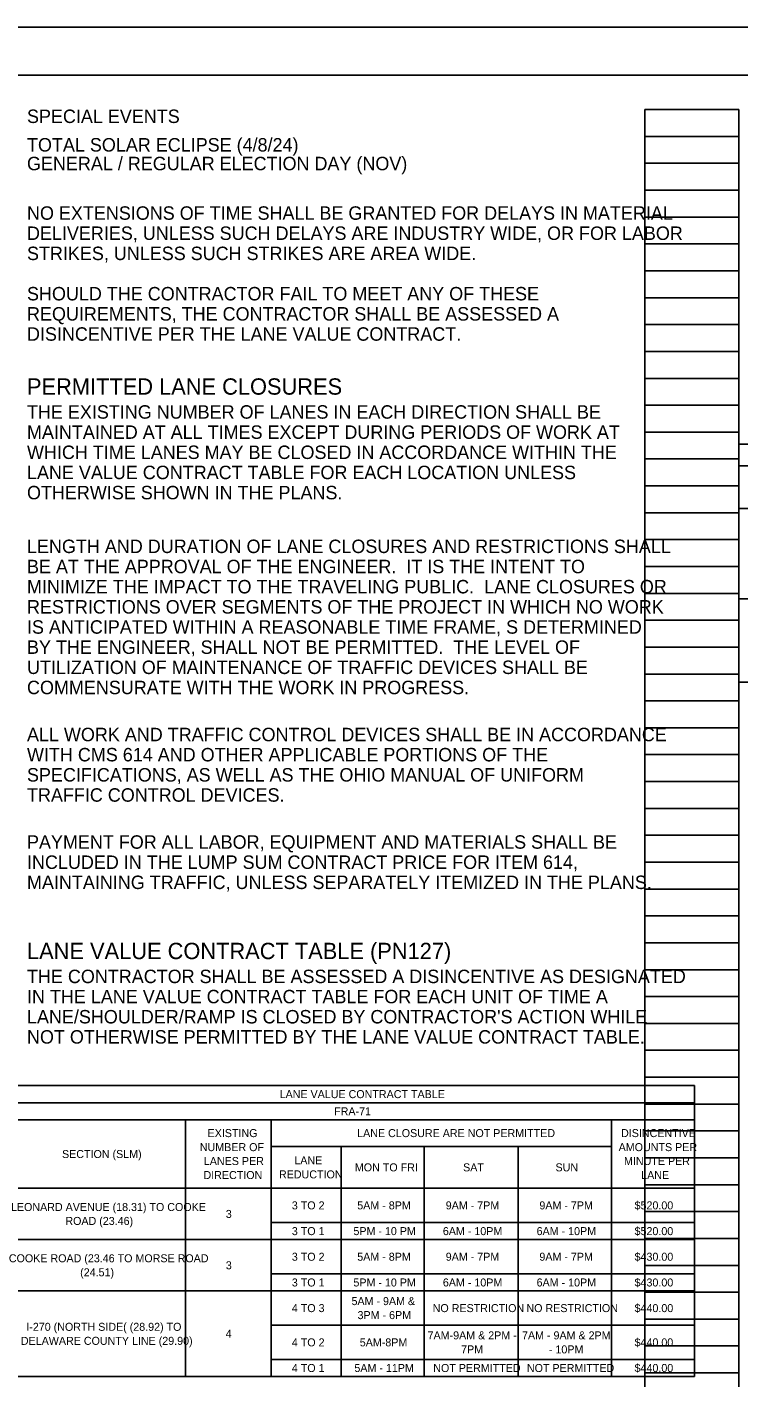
# Model space of a CAD drawing. Extents: x 0 to 34, y 0 to 22.
# Drawn here: x 17.24 to 24.66, y 7.93 to 22 of the extents above; entities that cross this region are included whole.
import ezdxf

# ---------------------------------------------------------------- set-up
doc = ezdxf.new("R2010")
doc.units = 0
for name, color, linetype in [('Default', 7, 'Continuous'), ('SH_Border', 7, 'Continuous'), ('SH_Cut_Line', 7, 'Continuous'), ('SH_Data', 7, 'Continuous'), ('SH_Text', 7, 'Continuous')]:
    doc.layers.add(name, color=color, linetype=linetype)

msp = doc.modelspace()

# ---------------------------------------------------------------- linework, layer by layer
at = {"layer": 'SH_Border'}
msp.add_lwpolyline([(1.5, 21.5), (33.5, 21.5), (33.5, 0.5), (1.5, 0.5)], close=True, dxfattribs=at)
at = {"layer": 'SH_Cut_Line'}
msp.add_lwpolyline([(0, 0), (34, 0), (34, 22), (0, 22)], close=True, dxfattribs=at)
at = {"layer": 'SH_Data'}
for p, q in [((23.68, 0.98), (23.68, 21.14)), ((23.68, 21.14), (24.66, 21.14)), ((24.66, 0.98), (24.66, 21.14)), ((23.68, 20.86), (24.66, 20.86)), ((23.68, 20.58), (24.66, 20.58)), ((23.68, 20.3), (24.66, 20.3)), ((23.68, 20.02), (24.66, 20.02)), ((23.68, 19.74), (24.66, 19.74)), ((23.68, 19.46), (24.66, 19.46)), ((23.68, 19.18), (24.66, 19.18)), ((23.68, 18.9), (24.66, 18.9)), ((23.68, 18.62), (24.66, 18.62)), ((23.68, 18.34), (24.66, 18.34)), ((23.68, 18.06), (24.66, 18.06)), ((23.68, 17.78), (24.66, 17.78)), ((24.658, 17.653), (31.092, 17.653)), ((24.658, 17.653), (24.658, 15.174)), ((23.68, 17.5), (24.66, 17.5)), ((24.658, 17.43), (31.092, 17.43)), ((23.68, 17.22), (24.66, 17.22)), ((23.68, 16.94), (24.66, 16.94)), ((24.658, 16.983), (31.092, 16.983)), ((23.68, 16.66), (24.66, 16.66)), ((23.68, 16.38), (24.66, 16.38)), ((23.68, 16.1), (24.66, 16.1)), ((24.658, 16.045), (31.092, 16.045)), ((23.68, 15.82), (24.66, 15.82)), ((23.68, 15.54), (24.66, 15.54)), ((23.68, 15.26), (24.66, 15.26)), ((24.658, 15.174), (31.092, 15.174)), ((23.68, 14.98), (24.66, 14.98)), ((23.68, 14.7), (24.66, 14.7)), ((23.68, 14.42), (24.66, 14.42)), ((23.68, 14.14), (24.66, 14.14)), ((23.68, 13.86), (24.66, 13.86)), ((23.68, 13.58), (24.66, 13.58)), ((23.68, 13.3), (24.66, 13.3)), ((23.68, 13.02), (24.66, 13.02)), ((23.68, 12.74), (24.66, 12.74)), ((23.68, 12.46), (24.66, 12.46)), ((23.68, 12.18), (24.66, 12.18)), ((23.68, 11.9), (24.66, 11.9)), ((23.68, 11.62), (24.66, 11.62)), ((23.68, 11.34), (24.66, 11.34)), ((23.68, 11.06), (24.66, 11.06)), ((17.029, 10.972), (24.197, 10.972)), ((24.197, 10.972), (24.197, 7.941)), ((17.029, 10.794), (24.197, 10.794)), ((23.68, 10.78), (24.66, 10.78)), ((17.029, 10.616), (24.197, 10.616)), ((18.892, 10.616), (18.892, 7.941)), ((19.784, 10.616), (19.784, 7.941)), ((23.332, 10.616), (23.332, 7.941)), ((23.68, 10.5), (24.66, 10.5)), ((19.784, 10.339), (23.332, 10.339)), ((20.515, 10.339), (20.515, 7.941)), ((21.379, 10.339), (21.379, 7.941)), ((22.36, 10.339), (22.36, 7.941)), ((23.68, 10.22), (24.66, 10.22)), ((17.029, 9.903), (24.197, 9.903)), ((23.68, 9.94), (24.66, 9.94)), ((23.68, 9.66), (24.66, 9.66)), ((19.784, 9.546), (24.197, 9.546)), ((17.029, 9.368), (24.197, 9.368)), ((23.68, 9.38), (24.66, 9.38)), ((19.784, 9.011), (24.197, 9.011)), ((23.68, 9.1), (24.66, 9.1)), ((17.029, 8.833), (24.197, 8.833)), ((23.68, 8.82), (24.66, 8.82)), ((19.784, 8.476), (24.197, 8.476)), ((23.68, 8.54), (24.66, 8.54)), ((23.68, 8.26), (24.66, 8.26)), ((19.784, 8.12), (24.197, 8.12)), ((17.029, 7.941), (24.197, 7.941)), ((23.68, 7.98), (24.66, 7.98))]:
    msp.add_line(p, q, dxfattribs=at)

# ---------------------------------------------------------------- texts
at = {"layer": 'Default'}
for s, p in [('SPECIAL EVENTS', (17.24, 21)), ('TOTAL SOLAR ECLIPSE (4/8/24)', (17.24, 20.703)), ('GENERAL / REGULAR ELECTION DAY (NOV)', (17.24, 20.508))]:
    msp.add_text(s, height=0.14, dxfattribs=at).set_placement(p)
at = {"layer": 'SH_Text'}
for s, height, p in [('NO EXTENSIONS OF TIME SHALL BE GRANTED FOR DELAYS IN MATERIAL ', 0.14, (17.24, 19.992)), ('DELIVERIES, UNLESS SUCH DELAYS ARE INDUSTRY WIDE, OR FOR LABOR ', 0.14, (17.24, 19.782)), ('STRIKES, UNLESS SUCH STRIKES ARE AREA WIDE.', 0.14, (17.24, 19.572)), ('SHOULD THE CONTRACTOR FAIL TO MEET ANY OF THESE ', 0.14, (17.24, 19.152)), ('REQUIREMENTS, THE CONTRACTOR SHALL BE ASSESSED A ', 0.14, (17.24, 18.942)), ('DISINCENTIVE PER THE LANE VALUE CONTRACT.', 0.14, (17.24, 18.732)), ('PERMITTED LANE CLOSURES', 0.17, (17.24, 18.17)), ('THE EXISTING NUMBER OF LANES IN EACH DIRECTION SHALL BE ', 0.14, (17.24, 17.92)), ('MAINTAINED AT ALL TIMES EXCEPT DURING PERIODS OF WORK AT ', 0.14, (17.24, 17.71)), ('WHICH TIME LANES MAY BE CLOSED IN ACCORDANCE WITHIN THE ', 0.14, (17.24, 17.5)), ('LANE VALUE CONTRACT TABLE FOR EACH LOCATION UNLESS ', 0.14, (17.24, 17.29)), ('OTHERWISE SHOWN IN THE PLANS.', 0.14, (17.24, 17.08)), ('LENGTH AND DURATION OF LANE CLOSURES AND RESTRICTIONS SHALL ', 0.14, (17.24, 16.52)), ('BE AT THE APPROVAL OF THE ENGINEER.  IT IS THE INTENT TO ', 0.14, (17.24, 16.31)), ('MINIMIZE THE IMPACT TO THE TRAVELING PUBLIC.  LANE CLOSURES OR ', 0.14, (17.24, 16.1)), ('RESTRICTIONS OVER SEGMENTS OF THE PROJECT IN WHICH NO WORK ', 0.14, (17.24, 15.89)), ('IS ANTICIPATED WITHIN A REASONABLE TIME FRAME, S DETERMINED ', 0.14, (17.24, 15.68)), ('BY THE ENGINEER, SHALL NOT BE PERMITTED.  THE LEVEL OF ', 0.14, (17.24, 15.47)), ('UTILIZATION OF MAINTENANCE OF TRAFFIC DEVICES SHALL BE ', 0.14, (17.24, 15.26)), ('COMMENSURATE WITH THE WORK IN PROGRESS.', 0.14, (17.24, 15.05)), ('ALL WORK AND TRAFFIC CONTROL DEVICES SHALL BE IN ACCORDANCE ', 0.14, (17.24, 14.56)), ('WITH CMS 614 AND OTHER APPLICABLE PORTIONS OF THE ', 0.14, (17.24, 14.35)), ('SPECIFICATIONS, AS WELL AS THE OHIO MANUAL OF UNIFORM ', 0.14, (17.24, 14.14)), ('TRAFFIC CONTROL DEVICES.', 0.14, (17.24, 13.93)), ('PAYMENT FOR ALL LABOR, EQUIPMENT AND MATERIALS SHALL BE ', 0.14, (17.24, 13.44)), ('INCLUDED IN THE LUMP SUM CONTRACT PRICE FOR ITEM 614, ', 0.14, (17.24, 13.23)), ('MAINTAINING TRAFFIC, UNLESS SEPARATELY ITEMIZED IN THE PLANS.', 0.14, (17.24, 13.02)), ('LANE VALUE CONTRACT TABLE (PN127)', 0.17, (17.24, 12.29)), ('THE CONTRACTOR SHALL BE ASSESSED A DISINCENTIVE AS DESIGNATED ', 0.14, (17.24, 12.04)), ('IN THE LANE VALUE CONTRACT TABLE FOR EACH UNIT OF TIME A ', 0.14, (17.24, 11.83)), ("LANE/SHOULDER/RAMP IS CLOSED BY CONTRACTOR'S ACTION WHILE ", 0.14, (17.24, 11.62)), ('NOT OTHERWISE PERMITTED BY THE LANE VALUE CONTRACT TABLE.', 0.14, (17.24, 11.41)), ('LANE VALUE CONTRACT TABLE', 0.08335, (19.873, 10.842)), ('FRA-71', 0.0834, (20.441, 10.663)), ('EXISTING ', 0.0834, (19.122, 10.436)), ('LANE CLOSURE ARE NOT PERMITTED', 0.08335, (20.681, 10.436)), ('DISINCENTIVE ', 0.08335, (23.431, 10.436)), ('SECTION (SLM)', 0.08335, (17.605, 10.218)), ('NUMBER OF ', 0.0834, (19.041, 10.29)), ('AMOUNTS PER ', 0.08335, (23.406, 10.29)), ('LANES PER ', 0.0834, (19.083, 10.145)), ('LANE ', 0.0834, (20.026, 10.152)), ('MON TO FRI', 0.0834, (20.657, 10.079)), ('SAT', 0.0834, (21.785, 10.079)), ('SUN', 0.0834, (22.748, 10.079)), ('MINUTE PER ', 0.08335, (23.462, 10.145)), ('DIRECTION', 0.0834, (19.079, 9.999)), ('REDUCTION', 0.0834, (19.866, 10.006)), ('LANE', 0.0834, (23.641, 9.999)), ('LEONARD AVENUE (18.31) TO COOKE ', 0.08335, (17.073, 9.666)), ('3 TO 2', 0.0834, (20, 9.683)), ('5AM - 8PM', 0.0834, (20.682, 9.683)), ('9AM - 7PM', 0.0834, (21.604, 9.683)), ('9AM - 7PM', 0.0834, (22.58, 9.683)), ('$520.00', 0.0834, (23.572, 9.683)), ('ROAD (23.46)', 0.08335, (17.64, 9.521)), ('3', 0.0834, (19.312, 9.594)), ('3 TO 1', 0.0834, (20, 9.415)), ('5PM - 10 PM', 0.08335, (20.642, 9.415)), ('6AM - 10PM', 0.0834, (21.574, 9.415)), ('6AM - 10PM', 0.0834, (22.551, 9.415)), ('$520.00', 0.0834, (23.572, 9.415)), ('COOKE ROAD (23.46 TO MORSE ROAD ', 0.08335, (17.051, 9.132)), ('3 TO 2', 0.0834, (20, 9.148)), ('5AM - 8PM', 0.0834, (20.682, 9.148)), ('9AM - 7PM', 0.0834, (21.604, 9.148)), ('9AM - 7PM', 0.0834, (22.58, 9.148)), ('$430.00', 0.0834, (23.572, 9.148)), ('(24.51)', 0.0834, (17.794, 8.986)), ('3', 0.0834, (19.312, 9.059)), ('3 TO 1', 0.0834, (20, 8.88)), ('5PM - 10 PM', 0.08335, (20.642, 8.88)), ('6AM - 10PM', 0.0834, (21.574, 8.88)), ('6AM - 10PM', 0.0834, (22.551, 8.88)), ('$430.00', 0.0834, (23.572, 8.88)), ('5AM - 9AM & ', 0.08335, (20.622, 8.686)), ('4 TO 3', 0.0834, (20, 8.613)), ('3PM - 6PM', 0.0834, (20.685, 8.54)), ('NO RESTRICTION', 0.08335, (21.468, 8.613)), ('NO RESTRICTION', 0.08335, (22.445, 8.613)), ('$440.00', 0.0834, (23.572, 8.613)), ('I-270 (NORTH SIDE( (28.92) TO ', 0.08335, (17.233, 8.418)), ('DELAWARE COUNTY LINE (29.90)', 0.08335, (17.176, 8.272)), ('4', 0.0834, (19.31, 8.345)), ('4 TO 2', 0.0834, (20, 8.256)), ('5AM-8PM', 0.0834, (20.708, 8.256)), ('7AM-9AM & 2PM - ', 0.08335, (21.415, 8.329)), ('7AM - 9AM & 2PM ', 0.08335, (22.399, 8.329)), ('$440.00', 0.0834, (23.572, 8.256)), ('7PM', 0.0834, (21.764, 8.183)), ('- 10PM', 0.0834, (22.679, 8.183)), ('4 TO 1', 0.0834, (20, 7.989)), ('5AM - 11PM', 0.0834, (20.652, 7.989)), ('NOT PERMITTED', 0.08335, (21.474, 7.989)), ('NOT PERMITTED', 0.08335, (22.45, 7.989)), ('$440.00', 0.0834, (23.572, 7.989))]:
    msp.add_text(s, height=height, dxfattribs=at).set_placement(p)

doc.saveas('drawing.dxf')
